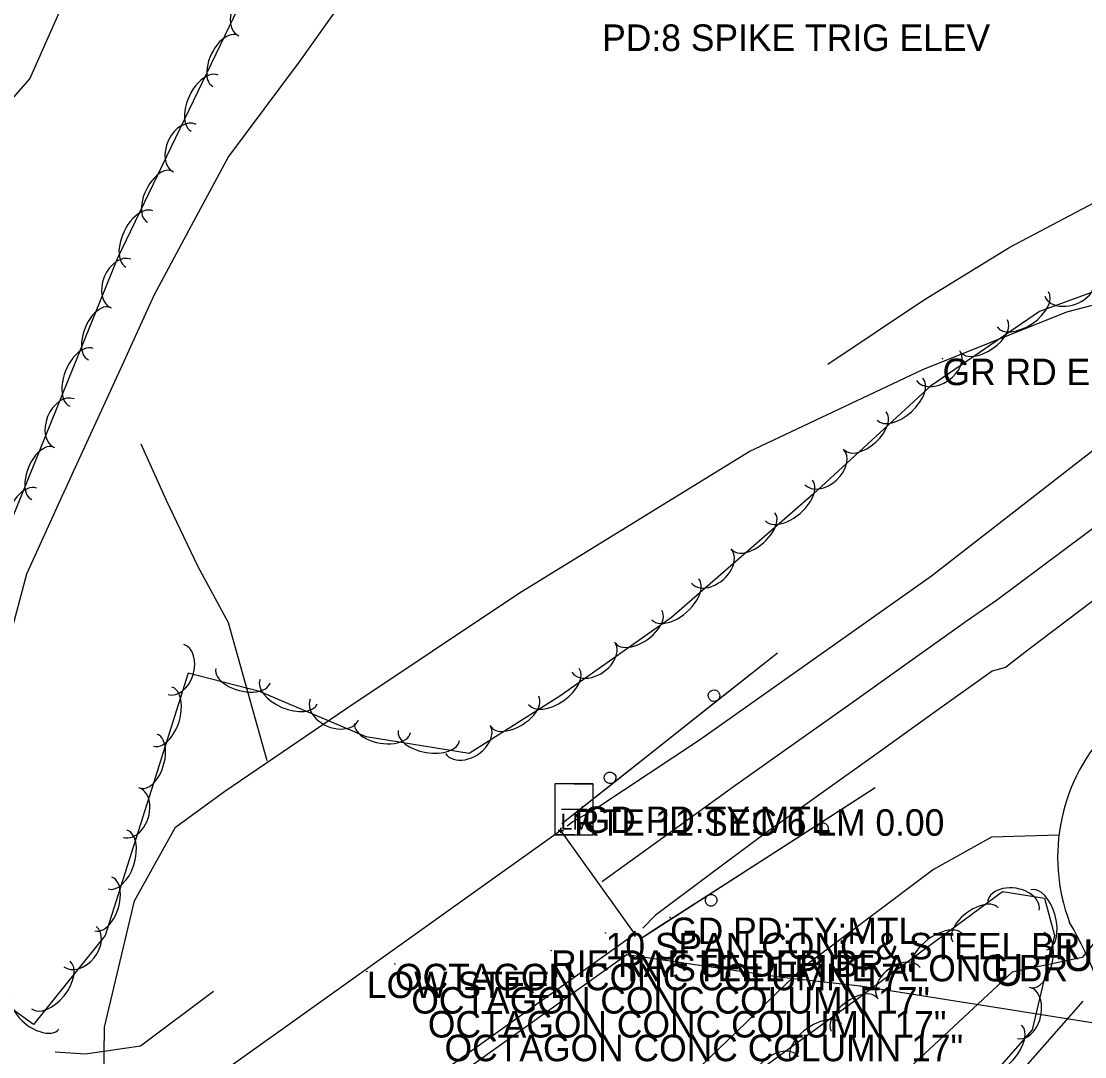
# Model space of a CAD drawing. Extents: x 1451369 to 1458940, y 1868647 to 1875095.
# Drawn here: x 1454437.4 to 1454638, y 1871624.7 to 1871820 of the extents above; entities that cross this region are included whole.
import ezdxf

# ---------------------------------------------------------------- set-up
doc = ezdxf.new("R2010")
doc.units = 0
for name, color, linetype in [('Default', 7, 'Continuous'), ('E_Existing_ROW', 7, 'Continuous'), ('E_No Plot', 7, 'Continuous'), ('E_Proposed ROW and Easements', 7, 'Continuous'), ('E_Quarter Section Line', 7, 'Continuous'), ('E_Row Point', 7, 'Continuous'), ('E_ROW Point Number', 7, 'Continuous'), ('E_Sheet Border', 7, 'Continuous'), ('E_Survey Point Number', 7, 'Continuous'), ('E_Tract Residual', 7, 'Continuous'), ('S_EDGE_PAVEMENT', 7, 'Continuous'), ('S_EXIST_ROW', 7, 'Continuous'), ('S_GUARDRAIL', 7, 'Continuous'), ('S_LOG_MILE_ANNOT', 7, 'Continuous'), ('S_MISC_STRUCTURES_ANNOT', 7, 'Continuous'), ('S_PARKING', 7, 'Continuous'), ('S_PAVEMENT_CROWN', 7, 'Continuous'), ('S_SECONDARY_CTL_ANNOT', 7, 'Continuous'), ('S_SURVEY_TEXT_ANNOT', 7, 'Continuous'), ('S_TRAILS', 7, 'Continuous'), ('S_WATER_UTILITIES_ANNOT', 7, 'Continuous')]:
    doc.layers.add(name, color=color, linetype=linetype)

msp = doc.modelspace()

# ---------------------------------------------------------------- linework, layer by layer
at = {"layer": 'E_Existing_ROW'}
for p, q in [((1454539.16, 1871667.36), (1454213.66, 1871435.13)), ((1454553.13, 1871647.85), (1454539.16, 1871667.36)), ((1454227.64, 1871415.7), (1454553.13, 1871647.85))]:
    msp.add_line(p, q, dxfattribs=at)
at = {"layer": 'E_No Plot'}
for points in [[(1454551.64, 1871643.91), (1454551.64, 1871643.96), (1454551.64, 1871643.91), (1454551.59, 1871643.91), (1454551.64, 1871643.91), (1454551.64, 1871643.86), (1454551.64, 1871643.91), (1454551.69, 1871643.91)], [(1454580.86, 1871639.64), (1454580.86, 1871639.69), (1454580.86, 1871639.64), (1454580.81, 1871639.64), (1454580.86, 1871639.64), (1454580.86, 1871639.59), (1454580.86, 1871639.64), (1454580.91, 1871639.64)], [(1454595.69, 1871638), (1454595.69, 1871638.05), (1454595.69, 1871638), (1454595.64, 1871638), (1454595.69, 1871638), (1454595.69, 1871637.95), (1454595.69, 1871638), (1454595.74, 1871638)]]:
    msp.add_lwpolyline(points, dxfattribs=at)
at = {"layer": 'E_Proposed ROW and Easements'}
for points in [[(1454611.18, 1871756.39), (1454611.18, 1871756.44), (1454611.18, 1871756.39), (1454611.13, 1871756.39), (1454611.18, 1871756.39), (1454611.18, 1871756.34), (1454611.18, 1871756.39), (1454611.23, 1871756.39)], [(1454543.27, 1871671.89), (1454543.27, 1871671.94), (1454543.27, 1871671.89), (1454543.22, 1871671.89), (1454543.27, 1871671.89), (1454543.27, 1871671.84), (1454543.27, 1871671.89), (1454543.32, 1871671.89)], [(1454559.78, 1871650.94), (1454559.78, 1871650.99), (1454559.78, 1871650.94), (1454559.73, 1871650.94), (1454559.78, 1871650.94), (1454559.78, 1871650.89), (1454559.78, 1871650.94), (1454559.83, 1871650.94)], [(1454547.61, 1871648.06), (1454547.61, 1871648.11), (1454547.61, 1871648.06), (1454547.56, 1871648.06), (1454547.61, 1871648.06), (1454547.61, 1871648.01), (1454547.61, 1871648.06), (1454547.66, 1871648.06)], [(1454537.34, 1871644.75), (1454537.34, 1871644.8), (1454537.34, 1871644.75), (1454537.29, 1871644.75), (1454537.34, 1871644.75), (1454537.34, 1871644.7), (1454537.34, 1871644.75), (1454537.39, 1871644.75)], [(1454507.87, 1871642.22), (1454507.87, 1871642.27), (1454507.87, 1871642.22), (1454507.82, 1871642.22), (1454507.87, 1871642.22), (1454507.87, 1871642.17), (1454507.87, 1871642.22), (1454507.92, 1871642.22)], [(1454502.57, 1871640.76), (1454502.57, 1871640.81), (1454502.57, 1871640.76), (1454502.52, 1871640.76), (1454502.57, 1871640.76), (1454502.57, 1871640.71), (1454502.57, 1871640.76), (1454502.62, 1871640.76)], [(1454510.95, 1871637.83), (1454510.95, 1871637.88), (1454510.95, 1871637.83), (1454510.9, 1871637.83), (1454510.95, 1871637.83), (1454510.95, 1871637.78), (1454510.95, 1871637.83), (1454511, 1871637.83)], [(1454514.07, 1871633.31), (1454514.07, 1871633.36), (1454514.07, 1871633.31), (1454514.02, 1871633.31), (1454514.07, 1871633.31), (1454514.07, 1871633.26), (1454514.07, 1871633.31), (1454514.12, 1871633.31)], [(1454517.22, 1871628.84), (1454517.22, 1871628.89), (1454517.22, 1871628.84), (1454517.17, 1871628.84), (1454517.22, 1871628.84), (1454517.22, 1871628.79), (1454517.22, 1871628.84), (1454517.27, 1871628.84)]]:
    msp.add_lwpolyline(points, dxfattribs=at)
at = {"layer": 'E_Quarter Section Line'}
for p, q in [((1454551.64, 1871643.91), (1454234.22, 1871417.39)), ((1454580.86, 1871639.64), (1454551.64, 1871643.91)), ((1454595.69, 1871638), (1454580.86, 1871639.64)), ((1454658.95, 1871627.97), (1454595.69, 1871638))]:
    msp.add_line(p, q, dxfattribs=at)
at = {"layer": 'E_Row Point'}
for points in [[(1454539.16, 1871667.36), (1454539.16, 1871667.86), (1454539.16, 1871667.36), (1454538.66, 1871667.36), (1454539.16, 1871667.36), (1454539.16, 1871666.86), (1454539.16, 1871667.36), (1454539.66, 1871667.36)], [(1454553.13, 1871647.85), (1454553.13, 1871648.35), (1454553.13, 1871647.85), (1454552.63, 1871647.85), (1454553.13, 1871647.85), (1454553.13, 1871647.35), (1454553.13, 1871647.85), (1454553.63, 1871647.85)]]:
    msp.add_lwpolyline(points, dxfattribs=at)
at = {"layer": 'E_ROW Point Number'}
for points in [[(1454738.31, 1871861.57), (1454708.8, 1871816.51), (1454693.32, 1871798.23), (1454669.26, 1871779.8), (1454629.46, 1871765.26), (1454608.9, 1871751.18), (1454586.75, 1871730.8), (1454560.06, 1871707.57), (1454538.95, 1871692.69), (1454521.86, 1871681.88), (1454502.43, 1871685.05), (1454482.33, 1871693.58), (1454468.83, 1871697.08), (1454462.33, 1871676.27), (1454453.21, 1871647.56), (1454439.65, 1871630.76), (1454428.53, 1871638.78), (1454420.08, 1871668), (1454435.67, 1871726.35), (1454455.54, 1871775.31), (1454484.24, 1871834.95)], [(1454466.05, 1871529.96), (1454507.82, 1871570.12), (1454546.16, 1871599.98), (1454595.25, 1871635.71), (1454622.47, 1871655.87), (1454630.45, 1871654.58), (1454632.33, 1871647.54), (1454628.1, 1871629.79), (1454610.02, 1871609.22), (1454579.17, 1871583.81), (1454543.54, 1871555.84), (1454533.41, 1871548.93), (1454494.55, 1871522.4), (1454482.82, 1871514.43), (1454469.55, 1871515.19), (1454464.89, 1871524.19), (1454466.39, 1871530.13)]]:
    msp.add_lwpolyline(points, dxfattribs=at)
for centre, major_axis, ratio, start_param, end_param in [((1454480.53, 1871821.74), (-2.15, -4.47), 0.685244, 3.141543, 6.283135), ((1454475.82, 1871812.57), (-2.32, -4.82), 0.540647, 3.141563, 6.283156), ((1454471.98, 1871804.58), (-2.54, -5.29), 0.550027, 3.141562, 6.283155), ((1454468.2, 1871796.12), (-2.15, -4.47), 0.685244, 3.141543, 6.283135), ((1454463.5, 1871786.95), (-2.32, -4.82), 0.540647, 3.141563, 6.283156), ((1454459.65, 1871778.96), (-2.54, -5.29), 0.550027, 3.141562, 6.283155), ((1454456.17, 1871770.54), (-1.86, -4.59), 0.685239, 3.141569, 6.283161), ((1454635.12, 1871769.87), (4.65, 1.7), 0.685298, 3.141594, 6.283187), ((1454626.31, 1871765.68), (4.84, 3.32), 0.550055, 3.141593, 6.283185), ((1454452.06, 1871761.09), (-2.01, -4.95), 0.540643, 3.141578, 6.283171), ((1454619, 1871760.66), (4.41, 3.02), 0.540675, 3.141593, 6.283185), ((1454448.72, 1871752.87), (-2.21, -5.44), 0.550022, 3.141578, 6.283171), ((1454610.35, 1871755.06), (4.09, 2.8), 0.68528, 3.141593, 6.283185), ((1454603.15, 1871748.76), (4.32, 3.97), 0.550046, 3.141593, 6.283185), ((1454445.48, 1871744.2), (-1.86, -4.59), 0.685239, 3.141569, 6.283161), ((1454596.62, 1871742.76), (3.93, 3.62), 0.540666, 3.141593, 6.283185), ((1454441.37, 1871734.75), (-2.01, -4.95), 0.540643, 3.141578, 6.283171), ((1454588.86, 1871735.97), (3.65, 3.36), 0.685269, 3.141593, 6.283185), ((1454438.03, 1871726.53), (-2.21, -5.44), 0.550022, 3.141578, 6.283171), ((1454582.19, 1871729.64), (4.43, 3.85), 0.55005, 3.141567, 6.28316), ((1454575.5, 1871723.82), (4.03, 3.51), 0.540671, 3.141568, 6.283161), ((1454567.56, 1871717.25), (3.74, 3.25), 0.685274, 3.141551, 6.283144), ((1454560.75, 1871710.98), (4.43, 3.85), 0.55005, 3.141567, 6.28316), ((1454553.84, 1871705.78), (4.37, 3.08), 0.540868, 3.141397, 6.28299), ((1454466.54, 1871697.74), (1.47, 4.71), 0.687736, 3.139936, 6.281528), ((1454545.28, 1871700.06), (4.05, 2.85), 0.685525, 3.141261, 6.282854), ((1454479.2, 1871696.58), (5.13, -1.33), 0.54495, 3.141876, 6.283469), ((1454537.86, 1871694.52), (4.79, 3.38), 0.550252, 3.141391, 6.282983), ((1454464.04, 1871688.86), (1.74, 5.58), 0.552027, 3.140584, 6.282177), ((1454487.81, 1871693.56), (5.4, -2.29), 0.550246, 3.141694, 6.283286), ((1454496.43, 1871690.18), (4.56, -1.94), 0.685518, 3.141758, 6.283351), ((1454530.46, 1871689.83), (4.52, 2.86), 0.540678, 3.141582, 6.283175), ((1454505.51, 1871686.7), (5.28, -0.86), 0.540718, 3.141602, 6.283195), ((1454514.26, 1871685.27), (5.79, -0.94), 0.550098, 3.141603, 6.283195), ((1454521.61, 1871684.54), (4.19, 2.65), 0.685284, 3.141575, 6.283168), ((1454461.4, 1871680.42), (1.59, 5.09), 0.542614, 3.140616, 6.282209), ((1454458.07, 1871670.75), (1.48, 4.69), 0.689813, 3.139333, 6.280926), ((1454455.54, 1871661.9), (1.76, 5.56), 0.553695, 3.140222, 6.281814), ((1454452.87, 1871653.5), (1.6, 5.06), 0.544253, 3.140265, 6.281858), ((1454624.55, 1871653.15), (-4.89, 0.79), 0.677031, 3.140863, 6.282456), ((1454629.36, 1871650.5), (-1.51, 5.67), 0.544521, 3.141593, 6.283185), ((1454617.4, 1871649.57), (-4.29, -3.19), 0.521797, 3.138474, 6.280067), ((1454448.45, 1871645.46), (3.05, 3.8), 0.696494, 3.138531, 6.280123), ((1454610.27, 1871644.29), (-4.71, -3.5), 0.530849, 3.138378, 6.279971), ((1454629.1, 1871642.91), (1.25, 5.2), 0.526207, 3.145438, 6.28703), ((1454442.93, 1871638.21), (3.62, 4.5), 0.559058, 3.139752, 6.281344), ((1454602.98, 1871638.58), (-3.97, -2.96), 0.661348, 3.13648, 6.278073), ((1454626.47, 1871632.95), (1.17, 4.81), 0.666934, 3.14794, 6.289533), ((1454440.17, 1871633), (4.29, -3.09), 0.546933, 3.142562, 6.284155), ((1454594.52, 1871632.65), (-4.31, -3.16), 0.522222, 3.133582, 6.275174), ((1454587.36, 1871627.43), (-4.73, -3.47), 0.531281, 3.133334, 6.274927), ((1454622.24, 1871626.22), (3.87, 4.41), 0.530273, 3.141649, 6.283241), ((1454580.02, 1871621.78), (-3.98, -2.95), 0.661859, 3.128451, 6.270044)]:
    msp.add_ellipse(centre, major_axis=major_axis, ratio=ratio, start_param=start_param, end_param=end_param, dxfattribs=at)
at = {"layer": 'E_Sheet Border'}
for p, q in [((1454541.66, 1871676.18), (1454545.26, 1871676.18)), ((1454539.26, 1871671.38), (1454544.06, 1871671.38)), ((1454541.66, 1871666.58), (1454538.06, 1871666.58))]:
    msp.add_line(p, q, dxfattribs=at)
msp.add_lwpolyline([(1454545.26, 1871676.18), (1454538.06, 1871676.18), (1454538.06, 1871666.58), (1454545.26, 1871666.58)], close=True, dxfattribs=at)
at = {"layer": 'E_Survey Point Number'}
for p, q in [((1454643.32, 1871650.46), (1454637.54, 1871643.41)), ((1454637.54, 1871643.41), (1454624.29, 1871640.62)), ((1454624.29, 1871640.62), (1454579.31, 1871598.81))]:
    msp.add_line(p, q, dxfattribs=at)
at = {"layer": 'E_Tract Residual'}
msp.add_lwpolyline([(1454498.03, 1871823.94), (1454489.77, 1871812.38), (1454476.47, 1871794.52), (1454469.43, 1871781.42), (1454462.38, 1871768.33), (1454456.37, 1871755.18), (1454450.35, 1871742.03), (1454444.34, 1871728.88), (1454438.33, 1871715.73), (1454431.88, 1871691.6)], dxfattribs=at)
at = {"layer": 'S_EDGE_PAVEMENT'}
for points in [[(1454761.69, 1871860.1), (1454746.95, 1871841.48), (1454738.24, 1871831.39), (1454729.52, 1871821.3), (1454719.14, 1871809.74), (1454710.5, 1871800.49), (1454694.1, 1871784.1), (1454684.53, 1871775.23), (1454674.42, 1871766.5), (1454666.44, 1871760.55), (1454660.2, 1871755.47), (1454648.09, 1871745.64), (1454628.58, 1871730.48), (1454609.07, 1871715.33), (1454598.13, 1871707.6), (1454587.2, 1871699.88), (1454576.26, 1871692.15), (1454565.32, 1871684.43), (1454546.17, 1871671.7), (1454541.43, 1871669), (1454540.33, 1871668.18)], [(1454754.88, 1871816.87), (1454745.54, 1871805.81), (1454735.93, 1871795.36), (1454726.32, 1871784.9), (1454718.41, 1871777.02), (1454709.37, 1871769.22), (1454694.86, 1871755.68), (1454689.05, 1871751.11), (1454689.49, 1871749.99), (1454684.2, 1871746), (1454683.23, 1871744.29), (1454671.26, 1871735.03), (1454661.4, 1871727.14), (1454644.34, 1871714.28), (1454627.27, 1871701.42), (1454623.09, 1871698.14), (1454620.54, 1871697.41), (1454609.79, 1871689.73), (1454599.04, 1871682.04), (1454588.3, 1871674.36), (1454577.55, 1871666.68), (1454567.24, 1871659.01), (1454556.93, 1871651.35), (1454554.66, 1871648.94)]]:
    msp.add_lwpolyline(points, dxfattribs=at)
at = {"layer": 'S_EXIST_ROW'}
for points in [[(1454589.54, 1871755.36), (1454607.61, 1871767.42), (1454623.89, 1871777.43), (1454645.48, 1871788.81), (1454666.35, 1871798.67), (1454679.64, 1871809.1), (1454692.92, 1871819.53), (1454705.5, 1871834.68), (1454700.05, 1871835.66)], [(1454428.57, 1871797.36), (1454438.96, 1871809.19), (1454447.38, 1871828.23)], [(1454473.61, 1871636.98), (1454459.84, 1871626.65), (1454449.5, 1871625.17), (1454443.76, 1871625.57)], [(1454637.64, 1871635.17), (1454625.86, 1871621.8), (1454614.08, 1871608.44), (1454602.3, 1871595.08), (1454590.52, 1871581.71), (1454579.84, 1871573.65), (1454569.16, 1871565.58), (1454560.65, 1871558.01), (1454555.73, 1871548.02), (1454536.22, 1871535.62)]]:
    msp.add_lwpolyline(points, dxfattribs=at)
at = {"layer": 'S_GUARDRAIL'}
for points in [[(1454539.32, 1871668.7), (1454580.07, 1871700.89)], [(1454578.55, 1871699.69), (1454580.07, 1871700.89)], [(1454568.74, 1871691.94), (1454578.55, 1871699.69)], [(1454549.13, 1871676.45), (1454568.74, 1871691.94)], [(1454539.32, 1871668.7), (1454549.13, 1871676.45)], [(1454598.46, 1871675.4), (1454554.24, 1871646.95)], [(1454598.46, 1871675.4), (1454587.95, 1871668.64)], [(1454587.95, 1871668.64), (1454566.92, 1871655.11)], [(1454566.92, 1871655.11), (1454556.41, 1871648.35)], [(1454556.41, 1871648.35), (1454554.24, 1871646.95)]]:
    msp.add_lwpolyline(points, dxfattribs=at)
for centre, major_axis, ratio in [((1454568.06, 1871692.81), (-0.682, 0.863), 0.999868), ((1454548.45, 1871677.31), (-0.682, 0.863), 0.999868), ((1454588.54, 1871667.71), (0.595, -0.925), 0.99999), ((1454567.52, 1871654.19), (0.595, -0.925), 0.99999)]:
    msp.add_ellipse(centre, major_axis=major_axis, ratio=ratio, dxfattribs=at)
at = {"layer": 'S_PARKING'}
for centre, major_axis, ratio, start_param, end_param in [((1454667.6, 1871662.35), (-4.04, -34.47), 0.999815, 4.045411, 5.192342), ((1454575.72, 1871615.11), (-28.7, 62.69), 0.999843, 4.107391, 4.814042)]:
    msp.add_ellipse(centre, major_axis=major_axis, ratio=ratio, start_param=start_param, end_param=end_param, dxfattribs=at)
at = {"layer": 'S_PAVEMENT_CROWN'}
msp.add_lwpolyline([(1454755.56, 1871834.56), (1454746.72, 1871824.06), (1454737.87, 1871813.57), (1454728.08, 1871803.15), (1454718.28, 1871792.74), (1454701.94, 1871776.45), (1454691.02, 1871766.3), (1454681.96, 1871758.27), (1454674.8, 1871752.2), (1454667.54, 1871746.1), (1454655.03, 1871735.92), (1454638.19, 1871723.34), (1454621.35, 1871710.76), (1454615.67, 1871706.77), (1454604.69, 1871698.97), (1454593.71, 1871691.17), (1454582.73, 1871683.38), (1454571.75, 1871675.58), (1454559.5, 1871666.75), (1454547.25, 1871657.93), (1454546.95, 1871657.7)], dxfattribs=at)
at = {"layer": 'S_TRAILS'}
for points in [[(1454452.76, 1871604.94), (1454453.07, 1871630.27), (1454458.72, 1871654.07), (1454466.48, 1871667.98), (1454475.78, 1871674.76), (1454498.57, 1871690.32), (1454531.15, 1871712.06), (1454574.69, 1871738.84), (1454607.46, 1871754.31), (1454634.61, 1871765.2), (1454664.57, 1871773.03), (1454675.34, 1871772.51), (1454679.89, 1871771.22)], [(1454483.77, 1871680.51), (1454476.45, 1871706.57), (1454470.69, 1871717.26), (1454464.76, 1871729.63), (1454460, 1871740.25)], [(1454633.14, 1871666.5), (1454620.4, 1871666.11), (1454609.48, 1871660.03), (1454584.95, 1871641.61), (1454552.82, 1871610.6), (1454495.73, 1871568.82), (1454476.2, 1871555.5), (1454470.45, 1871555.85), (1454464.28, 1871564.89), (1454461.53, 1871576.31)]]:
    msp.add_lwpolyline(points, dxfattribs=at)

# ---------------------------------------------------------------- texts
at = {"layer": 'Default'}
for p in [(1454633.91, 1871640.86), (1454620.66, 1871638.07)]:
    msp.add_text('U', height=6, rotation=360, dxfattribs=at).set_placement(p)
at = {"layer": 'E_Sheet Border'}
msp.add_text('LM', height=3, rotation=360, dxfattribs=at).set_placement((1454539.12, 1871667.53))
at = {"layer": 'S_LOG_MILE_ANNOT'}
msp.add_text('RTE 11 SEC 6 LM 0.00', height=5, dxfattribs=at).set_placement((1454541.66, 1871666.38))
at = {"layer": 'S_MISC_STRUCTURES_ANNOT'}
for s, p in [('OCTAGON CONC COLUMN 17"', (1454507.87, 1871637.22)), ('LOW STEEL', (1454502.57, 1871635.76)), ('OCTAGON CONC COLUMN 17"', (1454510.95, 1871632.83)), ('OCTAGON CONC COLUMN 17"', (1454514.07, 1871628.31)), ('OCTAGON CONC COLUMN 17"', (1454517.22, 1871623.84))]:
    msp.add_text(s, height=5, dxfattribs=at).set_placement(p)
at = {"layer": 'S_SECONDARY_CTL_ANNOT'}
msp.add_text('PD:8 SPIKE TRIG ELEV', height=5, dxfattribs=at).set_placement((1454546.96, 1871814.44))
at = {"layer": 'S_SURVEY_TEXT_ANNOT'}
for s, p in [('GR RD ENT TO BAYOU', (1454611.18, 1871751.39)), ('GD PD:TY:MTL', (1454543.27, 1871666.89)), ('GD PD:TY:MTL', (1454559.78, 1871645.94)), ('10 SPAN CONC & STEEL BR', (1454547.61, 1871643.06)), ('RIF RAF UNDER BR', (1454537.34, 1871639.75))]:
    msp.add_text(s, height=5, dxfattribs=at).set_placement(p)
at = {"layer": 'S_WATER_UTILITIES_ANNOT'}
msp.add_text('IN STEEL PIPE ALONG BR', height=5, dxfattribs=at).set_placement((1454551.64, 1871638.91))

doc.saveas('drawing.dxf')
